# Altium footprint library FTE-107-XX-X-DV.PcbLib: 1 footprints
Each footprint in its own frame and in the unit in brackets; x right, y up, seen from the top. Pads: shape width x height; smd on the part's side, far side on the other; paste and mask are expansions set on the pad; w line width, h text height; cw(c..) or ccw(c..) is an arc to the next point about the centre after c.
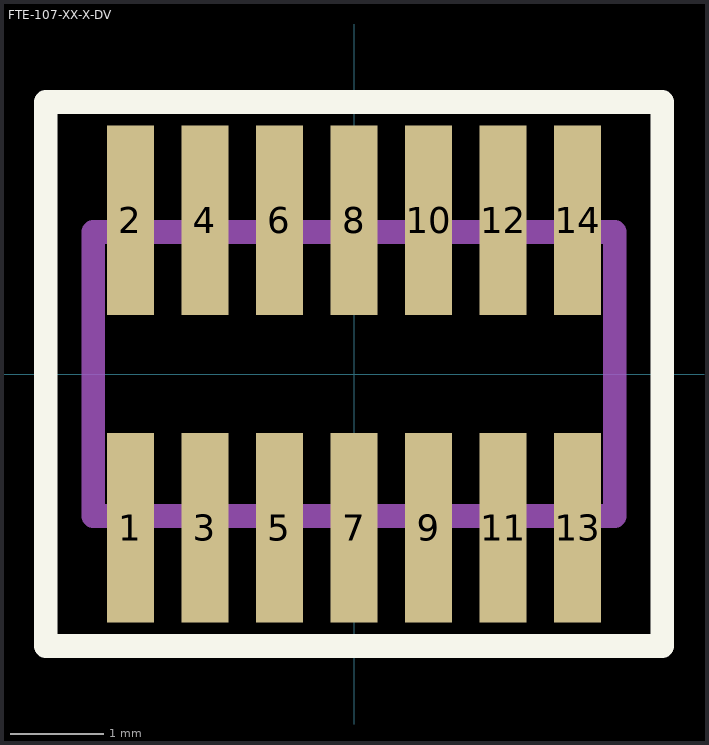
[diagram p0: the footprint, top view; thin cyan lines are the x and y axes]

## FTE-107-XX-X-DV [mil]
pads (14):
  rect 20x80 smd mask+2: 1(-94.5,-65) 2(-94.5,65) 3(-63,-65) 4(-63,65) 5(-31.5,-65) 6(-31.5,65) 7(0,-65) 8(0,65) 9(31.5,-65) 10(31.5,65) 11(63,-65) 12(63,65) 13(94.5,-65) 14(94.5,65)
Top Overlay:
  lines w10: -130.25,-115 130.25,-115 130.25,115 -130.25,115 -130.25,-115
Mechanical 1:
  lines w10: -110.25,-60 110.25,-60 110.25,60 -110.25,60 -110.25,-60
  text "J1" at -17.57,-18 h30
